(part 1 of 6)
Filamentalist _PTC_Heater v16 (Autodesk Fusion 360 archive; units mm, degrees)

design "Filamentalist _PTC_Heater" references "rocker switch 1", "Anycubic_Photon_Heater_Lid_v2", "heater element", "EL90005--STD--Power Supply 10A 12V (Bicolt Automática 120W)", "Mini Rocker Switch", "Switch,rocker,SPST,black,Iluminated", "1W1209WK", "Rocker Switch - Arcolectric R13 112C AAA"
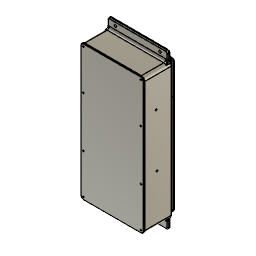
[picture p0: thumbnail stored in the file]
description: STEP AP203
part number: Anycubic Photo Heater Chassis v2
part number: Anycubic Photon Heater Lid
extrude "Extrude1" new body blind -2
extrude "Extrude2" new body blind 2
extrude "Extrude3" add blind 2
fillet "Fillet1" radius 2
extrude "Extrude4" cut blind 70
extrude "Extrude5" cut blind -20
offset_faces "OffsetFaces1" distance -0.5
offset_faces "OffsetFaces2" distance -0.5
offset_faces "OffsetFaces3" distance -0.5
offset_faces "OffsetFaces4" distance -0.5
scale "Scale1" ScaleFactor 0.97
extrude "Extrude6" cut blind -6
mirror "Mirror1"
move "Move1"
extrude "Extrude7" cut blind 100
move "Move2"
combine "Combine1"
extrude "Extrude9" cut distance 20
extrude "Extrude8" cut blind -10
move "Move3"
combine "Combine2"
extrude "Extrude10" new body blind 3
extrude "Extrude11" new body blind 3
extrude "Extrude12" new body blind 3
extrude "Extrude13" new body blind 3
extrude "Extrude14" new body blind 3
extrude "Extrude15" new body blind 3
extrude "Extrude16" new body blind 3
extrude "Extrude17" cut distance -340
move "Move4"
move "Move5"
combine "Combine3"
combine "Combine4"
extrude "Extrude18" cut blind -40
move "Move6"
extrude "Extrude19" add blind 10
extrude "Extrude20" new body blind 3
extrude "Extrude21" new body blind 3
extrude "Extrude22" new body blind 3
extrude "Extrude23" new body blind 3
extrude "Extrude24" new body blind 3
extrude "Extrude25" new body blind 3
component_insert "Component Insert4"
component_insert "Component Insert5"
component_insert "Component Insert6"
component_insert "Component Insert7"
component_insert "Component Insert8"
component_insert "Component Insert9"
remove_instance "RemoveInstance1"
component_insert "Component Insert10"
remove_instance "RemoveInstance2"
remove_instance "RemoveInstance3"
component_insert "Component Insert11"
remove_body "RemoveBody14"
remove_body "RemoveBody15"
remove_body "RemoveBody16"
remove_body "RemoveBody17"
remove_body "RemoveBody18"
remove_body "RemoveBody19"
remove_body "RemoveBody20"
remove_body "RemoveBody21"
remove_body "RemoveBody22"
remove_body "RemoveBody23"
remove_body "RemoveBody24"
remove_body "RemoveBody25"
remove_body "RemoveBody26"
remove_body "RemoveBody27"
remove_body "RemoveBody28"
base_feature "Base Feature1"
remove_instance "RemoveInstance4"
remove_instance "RemoveInstance5"
component_insert "Component Insert13"
position "Position5"
mirror "Mirror1" mirrorStitchTolerance 0.1
sketch "Sketch121" plane through (0, 129.2387, 0) normal (0, -1, 0) x axis (1, 0, 0)
  line L1 (48.1051, -74.1426) -> (50.0646, -75.3199)
  line L2 (57.2625, -58.9021) -> (48.1051, -74.1426)
  line L3 (59.222, -60.0795) -> (57.2625, -58.9021)
  line L4 (110.6429, 25.4992) -> (59.222, -60.0795)
  line L5 (111.3513, 73.7538) -> (111.3513, 28.0538)
  line L6 (-5.4087, 78.7138) -> (106.3913, 78.7138)
  line L7 (-10.3687, 55.8538) -> (-10.3687, 73.7538)
  line L8 (-7.8287, 55.8538) -> (-10.3687, 55.8538)
  line L9 (-7.8287, 22.1988) -> (-7.8287, 55.8538)
  line L10 (-10.3687, 22.1988) -> (-7.8287, 22.1988)
  line L11 (-10.3687, -6.9872) -> (-10.3687, 22.1988)
  line L12 (-4.5267, -6.9872) -> (-10.3687, -6.9872)
  line L13 (-4.5267, -36.7052) -> (-4.5267, -6.9872)
  line L14 (-10.3687, -36.7052) -> (-4.5267, -36.7052)
  line L15 (-10.3687, -64.1372) -> (-10.3687, -36.7052)
  line L16 (-4.5267, -64.1372) -> (-10.3687, -64.1372)
  line L17 (-4.5267, -93.8552) -> (-4.5267, -64.1372)
  line L18 (-10.3687, -93.8552) -> (-4.5267, -93.8552)
  line L19 (-10.3687, -103.2462) -> (-10.3687, -93.8552)
  line L20 (27.4983, -108.2062) -> (-5.4087, -108.2062)
  line L21 (50.0646, -75.3199) -> (31.7499, -105.8008)
  line L22 (71.2365, 31.181) -> (75.4807, 26.9368)
  line L23 (75.4808, 55.779) -> (71.2365, 51.5347)
  line L24 (44.602, 56.4579) -> (40.3585, 60.7014)
  line L25 (40.3585, 22.0143) -> (44.602, 26.2578)
  line L26 (45.2808, 25.579) -> (41.0373, 21.3355)
  line L27 (79.7243, 21.3355) -> (75.4809, 25.579)
  line L28 (69.8785, 31.1814) -> (65.6314, 35.4285)
  line L29 (55.1303, 35.4285) -> (50.8832, 31.1814)
  line L30 (59.7021, 41.3578) -> (55.1317, 45.9282)
  line L31 (55.1317, 36.7875) -> (59.7021, 41.3578)
  line L32 (66.3102, 36.1073) -> (70.5573, 31.8602)
  line L33 (70.5573, 50.8555) -> (66.3102, 46.6084)
  line L34 (61.0596, 41.3578) -> (65.63, 36.7875)
  line L35 (65.63, 45.9282) -> (61.0596, 41.3578)
  line L36 (65.6314, 47.2872) -> (69.8785, 51.5343)
  line L37 (50.8832, 51.5343) -> (55.1303, 47.2872)
  line L38 (60.3808, 42.0366) -> (64.9512, 46.607)
  line L39 (55.8105, 46.607) -> (60.3808, 42.0366)
  line L40 (41.0373, 61.3802) -> (45.2808, 57.1367)
  line L41 (75.4809, 57.1367) -> (79.7244, 61.3802)
  line L42 (70.5577, 52.2135) -> (74.802, 56.4578)
  line L43 (45.9597, 56.4578) -> (50.204, 52.2135)
  line L44 (60.3808, 40.6791) -> (55.8105, 36.1087)
  line L45 (64.9512, 36.1087) -> (60.3808, 40.6791)
  line L46 (45.281, 26.9368) -> (49.5252, 31.181)
  line L47 (49.5252, 51.5347) -> (45.2809, 55.779)
  line L48 (74.8019, 26.258) -> (70.5577, 30.5022)
  line L49 (50.204, 30.5022) -> (45.9598, 26.258)
  line L50 (50.2044, 31.8602) -> (54.4515, 36.1073)
  line L51 (54.4515, 46.6084) -> (50.2044, 50.8555)
  line L52 (76.1597, 26.2578) -> (80.4031, 22.0143)
  line L53 (80.4032, 60.7014) -> (76.1597, 56.4579)
  line L54 (133.3621, 41.3578) -> (104.5086, 41.3578)
  line L55 (133.3621, -4.4508) -> (133.3621, 41.3578)
  line L56 (104.5086, -4.4508) -> (133.3621, -4.4508)
  line L57 (104.5086, 41.3578) -> (104.5086, -4.4508)
  line L58 (150.5116, 41.3578) -> (104.5086, 41.3578)
  line L59 (150.5116, -14.1468) -> (150.5116, 41.3578)
  line L60 (104.5086, -14.1468) -> (150.5116, -14.1468)
  line L61 (104.5086, 41.3578) -> (104.5086, -14.1468)
  line L62 (100.5085, 41.3578) -> (104.5086, 41.3578)
  line L63 (100.5085, -14.1468) -> (100.5085, 41.3578)
  line L64 (104.5086, -14.1468) -> (100.5085, -14.1468)
  line L65 (104.5086, 41.3578) -> (104.5086, -14.1468)
  line L66 (50, -104.5945) -> (19.4151, -104.5945)
  line L67 (50, -130) -> (50, -104.5945)
  line L68 (19.4151, -130) -> (50, -130)
  line L69 (19.4151, -104.5945) -> (19.4151, -130)
  line L70 (31.7499, -99.5133) -> (100.5085, 13.6055)
  line L71 (27.4983, -108.2062) -> (31.7499, -99.5133)
  line L72 (50, -130) -> (117.9168, -14.1468)
  line L73 (236.4848, -122.3783) -> (150.5116, 16.8124)
  line L74 (221.251, -97.7148) -> (236.4848, -122.3783)
  line L75 (233.1462, -102.3471) -> (221.251, -97.7148)
  line L76 (237.9019, -110.0465) -> (233.1462, -102.3471)
  line L77 (237.9019, -132.6507) -> (237.9019, -110.0465)
  line L78 (185, -125) -> (237.9019, -132.6507)
  line L79 (138.8972, -14.1468) -> (185, -125)
  line L80 (25.5423, -99.5133) -> (32.8922, -97.1777)
  line L81 (19.4151, -104.5945) -> (25.5423, -99.5133)
  line L82 (34.9411, -96.5266) -> (32.3455, -97.3514)
  arc A1 centre (106.3913, 28.0538) radius 4.96 clockwise from (111.3513, 28.0538) to (110.6429, 25.4992)
  arc A2 centre (106.3913, 73.7538) radius 4.96 clockwise from (106.3913, 78.7138) to (111.3513, 73.7538)
  arc A3 centre (-5.4087, 73.7538) radius 4.96 clockwise from (-10.3687, 73.7538) to (-5.4087, 78.7138)
  arc A4 centre (-5.4087, -103.2462) radius 4.96 clockwise from (-5.4087, -108.2062) to (-10.3687, -103.2462)
  arc A5 centre (27.4983, -103.2462) radius 4.96 clockwise from (31.7499, -105.8008) to (27.4983, -108.2062)
  arc A6 centre (60.3808, 41.3579) radius 20.88 clockwise from (75.4808, 55.779) to (75.4807, 26.9368)
  arc A7 centre (60.3809, 41.3578) radius 14.88 clockwise from (71.2365, 51.5347) to (71.2365, 31.181)
  arc A8 centre (60.3808, 41.3579) radius 27.84 clockwise from (40.3585, 22.0143) to (40.3585, 60.7014)
  arc A9 centre (60.3809, 41.3578) radius 21.84 clockwise from (44.602, 26.2578) to (44.602, 56.4579)
  arc A10 centre (60.3808, 41.3579) radius 27.84 clockwise from (79.7243, 21.3355) to (41.0373, 21.3355)
  arc A11 centre (60.3809, 41.3578) radius 21.84 clockwise from (75.4809, 25.579) to (45.2808, 25.579)
  circle C1 centre (85.3808, 16.3578) radius 2.2
  arc A12 centre (60.3808, 41.3579) radius 7.92 clockwise from (65.6314, 35.4285) to (55.1303, 35.4285)
  arc A13 centre (60.3809, 41.3579) radius 13.92 clockwise from (69.8785, 31.1814) to (50.8832, 31.1814)
  arc A14 centre (60.3808, 41.3578) radius 6.96 clockwise from (55.1317, 36.7875) to (55.1317, 45.9282)
  arc A15 centre (60.3809, 41.3579) radius 13.92 clockwise from (70.5573, 50.8555) to (70.5573, 31.8602)
  arc A16 centre (60.3808, 41.3579) radius 7.92 clockwise from (66.3102, 46.6084) to (66.3102, 36.1073)
  arc A17 centre (60.3808, 41.3578) radius 6.96 clockwise from (65.63, 45.9282) to (65.63, 36.7875)
  arc A18 centre (60.3809, 41.3579) radius 13.92 clockwise from (50.8832, 51.5343) to (69.8785, 51.5343)
  arc A19 centre (60.3808, 41.3579) radius 7.92 clockwise from (55.1303, 47.2872) to (65.6314, 47.2872)
  arc A20 centre (60.3808, 41.3578) radius 6.96 clockwise from (55.8105, 46.607) to (64.9512, 46.607)
  arc A21 centre (60.3809, 41.3578) radius 21.84 clockwise from (45.2808, 57.1367) to (75.4809, 57.1367)
  arc A22 centre (60.3808, 41.3579) radius 27.84 clockwise from (41.0373, 61.3802) to (79.7244, 61.3802)
  arc A23 centre (60.3808, 41.3579) radius 20.88 clockwise from (45.9597, 56.4578) to (74.802, 56.4578)
  arc A24 centre (60.3809, 41.3578) radius 14.88 clockwise from (50.204, 52.2135) to (70.5577, 52.2135)
  arc A25 centre (60.3808, 41.3578) radius 6.96 clockwise from (64.9512, 36.1087) to (55.8105, 36.1087)
  circle C2 centre (85.3808, 66.3578) radius 2.2
  circle C3 centre (35.3808, 66.3578) radius 2.2
  circle C4 centre (35.3808, 16.3578) radius 2.2
  arc A26 centre (60.3809, 41.3578) radius 14.88 clockwise from (49.5252, 31.181) to (49.5252, 51.5347)
  arc A27 centre (60.3808, 41.3579) radius 20.88 clockwise from (45.281, 26.9368) to (45.2809, 55.779)
  arc A28 centre (60.3809, 41.3578) radius 14.88 clockwise from (70.5577, 30.5022) to (50.204, 30.5022)
  arc A29 centre (60.3808, 41.3579) radius 20.88 clockwise from (74.8019, 26.258) to (45.9598, 26.258)
  arc A30 centre (60.3808, 41.3579) radius 7.92 clockwise from (54.4515, 36.1073) to (54.4515, 46.6084)
  arc A31 centre (60.3809, 41.3579) radius 13.92 clockwise from (50.2044, 31.8602) to (50.2044, 50.8555)
  arc A32 centre (60.3808, 41.3579) radius 27.84 clockwise from (80.4032, 60.7014) to (80.4031, 22.0143)
  arc A33 centre (60.3809, 41.3578) radius 21.84 clockwise from (76.1597, 56.4579) to (76.1597, 26.2578)
  circle C5 centre (26.6464, -73.9162) radius 3.175
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  point P181 (100.5085, 13.6055)
  point P30 (27.4983, -108.2062)
  point P183 (27.4983, -108.2062)
  point P184 (117.9168, -14.1468)
  point P185 (150.5116, 16.8124)
  point P187 (221.251, -97.7148)
  point P192 (138.8972, -14.1468)
  point P195 (32.3455, -97.3514)
  horizontal L54
  vertical L55
  horizontal L56
  vertical L57
  horizontal L58
  vertical L59
  horizontal L60
  vertical L61
  horizontal L62
  vertical L63
  horizontal L64
  vertical L65
  horizontal L66
  vertical L67
  horizontal L68
  vertical L69
  midpoint L63 P181
  coincident P30 P183
  coincident L60 P184
  coincident L59 P185
  coincident L73 P187
  parallel L73 L76
  vertical L77
  coincident L60 P192
  coincident L80 P195
  parallel L80 L82
extrude "Extrude1" cut sketch "Sketch121" profile of L1 L2 L3 L4 A1 L5 L20 A5 L21 L54 L55 L56 L57 L58 L59 L60 L61 L62 L63 L64 L65 L66 L67 L68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 distance 120
remove_body "RemoveBody1"
remove_body "RemoveBody2"
sketch "Sketch122" plane through (0, 129.2387, 0) normal (0, -1, 0) x axis (1, 0, 0)
  line L1 (150.5116, 41.3578) -> (141.4313, 41.3578)
  line L2 (150.5116, 16.8124) -> (150.5116, 41.3578)
  line L3 (215.4468, -88.3178) -> (150.5116, 16.8124)
  line L4 (221.251, -97.7148) -> (216.1448, -89.4478)
  line L5 (233.1462, -102.3471) -> (221.251, -97.7148)
  line L6 (236.7652, -108.2062) -> (233.1462, -102.3471)
  line L7 (258.1913, -108.2062) -> (236.7652, -108.2062)
  line L8 (263.1513, -93.8552) -> (263.1513, -103.2462)
  line L9 (257.3093, -93.8552) -> (263.1513, -93.8552)
  line L10 (257.3093, -64.1372) -> (257.3093, -93.8552)
  line L11 (263.1513, -64.1372) -> (257.3093, -64.1372)
  line L12 (263.1513, -36.7052) -> (263.1513, -64.1372)
  line L13 (257.3093, -36.7052) -> (263.1513, -36.7052)
  line L14 (257.3093, -6.9872) -> (257.3093, -36.7052)
  line L15 (263.1513, -6.9872) -> (257.3093, -6.9872)
  line L16 (263.1513, 22.1988) -> (263.1513, -6.9872)
  line L17 (260.6113, 22.1988) -> (263.1513, 22.1988)
  line L18 (260.6113, 55.8538) -> (260.6113, 22.1988)
  line L19 (263.1513, 55.8538) -> (260.6113, 55.8538)
  line L20 (263.1513, 73.7538) -> (263.1513, 55.8538)
  line L21 (146.3913, 78.7138) -> (258.1913, 78.7138)
  line L22 (141.4313, 41.3578) -> (141.4313, 73.7538)
  line L23 (176.6229, 56.4579) -> (172.3795, 60.7014)
  line L24 (172.3795, 22.0143) -> (176.6229, 26.2578)
  line L25 (202.5782, 50.8555) -> (198.3312, 46.6084)
  line L26 (198.3312, 36.1073) -> (202.5782, 31.8602)
  line L27 (206.8229, 26.258) -> (202.5786, 30.5022)
  line L28 (182.2249, 30.5022) -> (177.9807, 26.258)
  line L29 (207.5017, 55.779) -> (203.2574, 51.5347)
  line L30 (203.2574, 31.181) -> (207.5017, 26.9368)
  line L31 (192.4018, 40.6791) -> (187.8314, 36.1087)
  line L32 (196.9721, 36.1087) -> (192.4018, 40.6791)
  line L33 (202.5786, 52.2135) -> (206.8229, 56.4578)
  line L34 (177.9807, 56.4578) -> (182.2249, 52.2135)
  line L35 (173.0583, 61.3802) -> (177.3017, 57.1367)
  line L36 (207.5018, 57.1367) -> (211.7453, 61.3802)
  line L37 (192.4018, 42.0366) -> (196.9721, 46.607)
  line L38 (187.8314, 46.607) -> (192.4018, 42.0366)
  line L39 (197.6524, 47.2872) -> (201.8994, 51.5343)
  line L40 (182.9041, 51.5343) -> (187.1512, 47.2872)
  line L41 (191.723, 41.3578) -> (187.1526, 45.9282)
  line L42 (187.1526, 36.7875) -> (191.723, 41.3578)
  line L43 (186.4724, 46.6084) -> (182.2253, 50.8555)
  line L44 (182.2253, 31.8602) -> (186.4724, 36.1073)
  line L45 (193.0806, 41.3578) -> (197.6509, 36.7875)
  line L46 (197.6509, 45.9282) -> (193.0806, 41.3578)
  line L47 (201.8994, 31.1814) -> (197.6524, 35.4285)
  line L48 (187.1512, 35.4285) -> (182.9041, 31.1814)
  line L49 (177.3017, 25.579) -> (173.0583, 21.3355)
  line L50 (211.7453, 21.3355) -> (207.5018, 25.579)
  line L51 (208.1806, 26.2578) -> (212.4241, 22.0143)
  line L52 (212.4241, 60.7014) -> (208.1806, 56.4579)
  line L53 (181.5461, 51.5347) -> (177.3019, 55.779)
  line L54 (177.3019, 26.9368) -> (181.5461, 31.181)
  line L55 (110, 110) -> (240, 110)
  line L56 (110, 0) -> (110, 110)
  line L57 (240, 0) -> (110, 0)
  line L58 (240, 110) -> (240, 0)
  circle C1 centre (241.5342, -100.5862) radius 3.175
  circle C2 centre (233.8352, -51.6912) radius 3.175
  circle C3 centre (226.1363, -47.2462) radius 3.175
  circle C4 centre (226.1363, -38.3562) radius 3.175
  circle C5 centre (218.4373, -33.9112) radius 3.175
  circle C6 centre (218.4373, -25.0212) radius 3.175
  circle C7 centre (210.7383, -20.5762) radius 3.175
  circle C8 centre (249.2332, -69.4712) radius 3.175
  circle C9 centre (249.2332, -60.5812) radius 3.175
  circle C10 centre (233.8352, -60.5812) radius 3.175
  circle C11 centre (241.5342, -65.0262) radius 3.175
  circle C12 centre (241.5342, -73.9162) radius 3.175
  circle C13 centre (249.2332, -78.3612) radius 3.175
  circle C14 centre (203.0394, -25.0212) radius 3.175
  circle C15 centre (210.7383, -29.4662) radius 3.175
  circle C16 centre (210.7383, -38.3562) radius 3.175
  circle C17 centre (218.4373, -42.8012) radius 3.175
  circle C18 centre (249.2332, -33.9112) radius 3.175
  circle C19 centre (233.8352, -25.0212) radius 3.175
  circle C20 centre (241.5342, -29.4662) radius 3.175
  circle C21 centre (241.5342, -38.3562) radius 3.175
  circle C22 centre (249.2332, -25.0212) radius 3.175
  circle C23 centre (241.5342, -20.5762) radius 3.175
  circle C24 centre (241.5342, -56.1362) radius 3.175
  circle C25 centre (241.5342, -47.2462) radius 3.175
  circle C26 centre (233.8352, -42.8012) radius 3.175
  circle C27 centre (233.8352, -33.9112) radius 3.175
  circle C28 centre (226.1363, -29.4662) radius 3.175
  circle C29 centre (226.1363, -20.5762) radius 3.175
  circle C30 centre (249.2332, -51.6912) radius 3.175
  circle C31 centre (249.2332, -42.8012) radius 3.175
  circle C32 centre (226.1363, -82.8062) radius 3.175
  circle C33 centre (233.8352, -87.2512) radius 3.175
  circle C34 centre (241.5342, -91.6962) radius 3.175
  circle C35 centre (249.2332, -96.1412) radius 3.175
  circle C36 centre (187.6414, -25.0212) radius 3.175
  circle C37 centre (187.6414, -33.9112) radius 3.175
  circle C38 centre (195.3404, -38.3562) radius 3.175
  circle C39 centre (195.3404, -47.2462) radius 3.175
  circle C40 centre (203.0394, -51.6912) radius 3.175
  circle C41 centre (203.0394, -60.5812) radius 3.175
  circle C42 centre (210.7383, -65.0262) radius 3.175
  circle C43 centre (210.7383, -73.9162) radius 3.175
  circle C44 centre (218.4373, -78.3612) radius 3.175
  arc A1 centre (218.4373, -87.2512) radius 3.175 clockwise from (215.4468, -88.3178) to (216.1448, -89.4478)
  arc A2 centre (258.1913, -103.2462) radius 4.96 clockwise from (263.1513, -103.2462) to (258.1913, -108.2062)
  arc A3 centre (258.1913, 73.7538) radius 4.96 clockwise from (258.1913, 78.7138) to (263.1513, 73.7538)
  arc A4 centre (146.3913, 73.7538) radius 4.96 clockwise from (141.4313, 73.7538) to (146.3913, 78.7138)
  circle C45 centre (226.1363, -91.6962) radius 3.175
  circle C46 centre (233.8352, -96.1412) radius 3.175
  circle C47 centre (233.8352, -78.3612) radius 3.175
  circle C48 centre (241.5342, -82.8062) radius 3.175
  circle C49 centre (249.2332, -87.2512) radius 3.175
  circle C50 centre (195.3404, -20.5762) radius 3.175
  circle C51 centre (233.8352, -69.4712) radius 3.175
  circle C52 centre (226.1363, -65.0262) radius 3.175
  circle C53 centre (226.1363, -56.1362) radius 3.175
  circle C54 centre (218.4373, -51.6912) radius 3.175
  circle C55 centre (195.3404, -29.4662) radius 3.175
  circle C56 centre (203.0394, -33.9112) radius 3.175
  circle C57 centre (203.0394, -42.8012) radius 3.175
  circle C58 centre (210.7383, -47.2462) radius 3.175
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  horizontal L55
  vertical L56
  horizontal L57
  vertical L58
extrude "Extrude2" cut sketch "Sketch122" distance 60
delete_face "DeleteFace1"
delete_face "DeleteFace2"
delete_face "DeleteFace3"
delete_face "DeleteFace4"
delete_face "DeleteFace5"
delete_face "DeleteFace6"
delete_face "DeleteFace7"
sketch "Sketch123" plane through (263.1513, 0, 0) normal (-1, 0, 0) x axis (0, -1, 0)
  line L1 (-85.2967, 73.7538) -> (-85.2967, 52.2724)
  line L2 (-129.2387, 73.7538) -> (-85.2967, 73.7538)
  line L3 (-129.2387, -103.2462) -> (-129.2387, 73.7538)
  line L4 (-85.2967, -103.2462) -> (-129.2387, -103.2462)
  line L5 (-85.2967, 25.7802) -> (-85.2967, -103.2462)
  line L6 (-77.2576, 25.7802) -> (-85.2967, 25.7802)
  line L7 (-77.2576, 52.2724) -> (-77.2576, 25.7802)
  line L8 (-85.2967, 52.2724) -> (-77.2576, 52.2724)
  line L9 (-85.2967, 65.0066) -> (-122.5621, 65.0066)
  line L10 (-85.2967, -94.8647) -> (-85.2967, 65.0066)
  line L11 (-122.5621, -94.8647) -> (-85.2967, -94.8647)
  line L12 (-122.5621, 65.0066) -> (-122.5621, -94.8647)
  point P12 (-85.2967, -94.8647)
  horizontal L9
  vertical L10
  horizontal L11
  vertical L12
  coincident L5 P12
extrude "Extrude3" cut sketch "Sketch123" profile of L1 L5 L9 L10 L11 L12 against normal blind 20
sketch "Sketch124" plane through (265.6913, 0, 0) normal (1, 0, 0) x axis (0, 1, 0)
  line L1 (85.2967, -61.2162) -> (85.2967, -71.7583)
  line L2 (85.072, -61.2162) -> (85.2967, -61.2162)
  line L3 (85.072, -59.5646) -> (85.072, -61.2162)
  curve K1 (85.072, -59.5646) -> (84.1256, -57.0155)
  curve K2 (84.1256, -57.0155) -> (83.4601, -57.2521)
  line L4 (83.1182, -55.8584) -> (83.4601, -57.2521)
  curve K3 (83.1182, -55.8584) -> (83.9654, -55.5501)
  curve K4 (83.9654, -55.5501) -> (85.072, -56.4247)
  line L5 (85.072, -55.6478) -> (85.072, -56.4247)
  line L6 (85.2967, -55.6478) -> (85.072, -55.6478)
  line L7 (85.2967, -29.0841) -> (85.2967, -55.6478)
  line L8 (85.2967, -4.0662) -> (85.2967, -14.6083)
  line L9 (84.5836, -4.0662) -> (85.2967, -4.0662)
  line L10 (84.5836, -2.4146) -> (84.5836, -4.0662)
  curve K5 (84.5836, -2.4146) -> (83.6372, 0.1345)
  curve K6 (83.6372, 0.1345) -> (82.9717, -0.1021)
  line L11 (82.6297, 1.2916) -> (82.9717, -0.1021)
  curve K7 (82.6297, 1.2916) -> (83.4769, 1.5999)
  curve K8 (83.4769, 1.5999) -> (84.5836, 0.7253)
  line L12 (84.5836, 1.5022) -> (84.5836, 0.7253)
  line L13 (85.2967, 1.5022) -> (84.5836, 1.5022)
  line L14 (85.2967, 65.0066) -> (85.2967, 1.5022)
  line L15 (122.5621, 65.0066) -> (85.2967, 65.0066)
  line L16 (122.5621, -94.8647) -> (122.5621, 65.0066)
  line L17 (85.2967, -94.8647) -> (122.5621, -94.8647)
  line L18 (85.2967, -86.2341) -> (85.2967, -94.8647)
  line L19 (127.2387, 73.7538) -> (127.2387, -103.2462)
  line L20 (72.0887, 73.7538) -> (127.2387, 73.7538)
  line L21 (72.0887, -103.2462) -> (72.0887, 73.7538)
  line L22 (127.2387, -103.2462) -> (72.0887, -103.2462)
  line L23 (80, 11.4296) -> (85.2967, 11.4296)
  line L24 (80, -90) -> (80, 11.4296)
  line L25 (85.2967, -90) -> (80, -90)
  line L26 (85.2967, 11.4296) -> (85.2967, -90)
  arc A1 centre (99.1397, -21.8462) radius 15.621 clockwise from (85.2967, -29.0841) to (85.2967, -14.6083)
  arc A2 centre (99.1397, -78.9962) radius 15.621 clockwise from (85.2967, -86.2341) to (85.2967, -71.7583)
  point P36 (85.2967, 11.4296)
  horizontal L23
  vertical L24
  horizontal L25
  vertical L26
  coincident L14 P36
extrude "Extrude4" cut sketch "Sketch124" profile of L1 L2 L3 K1 K2 L4 K3 K4 L5 L6 L7 A1 L8 L9 L10 K5 K6 L11 K7 K8 L12 L13 L14 L18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 against normal blind 1
delete_face "DeleteFace8"
delete_face "DeleteFace9"
delete_face "DeleteFace10"
delete_face "DeleteFace11"
sketch "Sketch125" plane through (0, 0, 52.2724) normal (0, 0, -1) x axis (1, 0, 0)
  line L1 (262.2877, -84.4331) -> (262.2877, -77.2576)
  line L2 (263.1513, -85.2967) -> (262.2877, -84.4331)
  line L3 (263.1513, -77.2576) -> (263.1513, -85.2967)
  line L4 (262.2877, -77.2576) -> (263.1513, -77.2576)
extrude "Extrude5" add sketch "Sketch125" along normal blind 28
move "Move1"
sketch "Sketch126" plane through (0, 129.2387, 0) normal (0, -1, 0) x axis (1, 0, 0)
  line L1 (111.1513, 73.7538) -> (111.1513, -103.2462)
  line L2 (88, 78.7138) -> (106.1913, 78.7138)
  line L3 (88, 0) -> (88, 78.7138)
  line L4 (8.896, 0) -> (88, 0)
  line L5 (63.4468, -88.3178) -> (8.896, 0)
  line L6 (69.251, -97.7148) -> (64.1448, -89.4478)
  line L7 (81.1462, -102.3471) -> (69.251, -97.7148)
  line L8 (84.7652, -108.2062) -> (81.1462, -102.3471)
  line L9 (106.1913, -108.2062) -> (84.7652, -108.2062)
  arc A1 centre (106.1913, 73.7538) radius 4.96 clockwise from (106.1913, 78.7138) to (111.1513, 73.7538)
  arc A2 centre (66.4373, -87.2512) radius 3.175 clockwise from (63.4468, -88.3178) to (64.1448, -89.4478)
  arc A3 centre (106.1913, -103.2462) radius 4.96 clockwise from (111.1513, -103.2462) to (106.1913, -108.2062)
  circle C1 centre (89.5342, -91.6962) radius 3.175
  circle C2 centre (74.1363, -73.9162) radius 3.175
  circle C3 centre (66.4373, -69.4712) radius 3.175
  circle C4 centre (66.4373, -60.5812) radius 3.175
  circle C5 centre (58.7383, -56.1362) radius 3.175
  circle C6 centre (58.7383, -47.2462) radius 3.175
  circle C7 centre (51.0394, -42.8012) radius 3.175
  circle C8 centre (51.0394, -33.9112) radius 3.175
  circle C9 centre (43.3404, -29.4662) radius 3.175
  circle C10 centre (66.4373, -51.6912) radius 3.175
  circle C11 centre (74.1363, -56.1362) radius 3.175
  circle C12 centre (74.1363, -65.0262) radius 3.175
  circle C13 centre (81.8352, -69.4712) radius 3.175
  circle C14 centre (43.3404, -20.5762) radius 3.175
  circle C15 centre (97.2332, -87.2512) radius 3.175
  circle C16 centre (89.5342, -82.8062) radius 3.175
  circle C17 centre (81.8352, -78.3612) radius 3.175
  circle C18 centre (81.8352, -96.1412) radius 3.175
  circle C19 centre (74.1363, -91.6962) radius 3.175
  circle C20 centre (66.4373, -78.3612) radius 3.175
  circle C21 centre (58.7383, -73.9162) radius 3.175
  circle C22 centre (58.7383, -65.0262) radius 3.175
  circle C23 centre (51.0394, -60.5812) radius 3.175
  circle C24 centre (51.0394, -51.6912) radius 3.175
  circle C25 centre (43.3404, -47.2462) radius 3.175
  circle C26 centre (43.3404, -38.3562) radius 3.175
  circle C27 centre (35.6414, -33.9112) radius 3.175
  circle C28 centre (35.6414, -25.0212) radius 3.175
  circle C29 centre (97.2332, -96.1412) radius 3.175
  circle C30 centre (81.8352, -87.2512) radius 3.175
  circle C31 centre (74.1363, -82.8062) radius 3.175
  circle C32 centre (97.2332, -42.8012) radius 3.175
  circle C33 centre (97.2332, -51.6912) radius 3.175
  circle C34 centre (74.1363, -20.5762) radius 3.175
  circle C35 centre (74.1363, -29.4662) radius 3.175
  circle C36 centre (81.8352, -33.9112) radius 3.175
  circle C37 centre (81.8352, -42.8012) radius 3.175
  circle C38 centre (89.5342, -47.2462) radius 3.175
  circle C39 centre (89.5342, -56.1362) radius 3.175
  circle C40 centre (89.5342, -20.5762) radius 3.175
  circle C41 centre (97.2332, -25.0212) radius 3.175
  circle C42 centre (89.5342, -29.4662) radius 3.175
  circle C43 centre (81.8352, -25.0212) radius 3.175
  circle C44 centre (66.4373, -42.8012) radius 3.175
  circle C45 centre (58.7383, -38.3562) radius 3.175
  circle C46 centre (58.7383, -29.4662) radius 3.175
  circle C47 centre (51.0394, -25.0212) radius 3.175
  circle C48 centre (97.2332, -78.3612) radius 3.175
  circle C49 centre (89.5342, -73.9162) radius 3.175
  circle C50 centre (89.5342, -65.0262) radius 3.175
  circle C51 centre (81.8352, -60.5812) radius 3.175
  circle C52 centre (97.2332, -60.5812) radius 3.175
  circle C53 centre (97.2332, -69.4712) radius 3.175
  circle C54 centre (58.7383, -20.5762) radius 3.175
  circle C55 centre (66.4373, -25.0212) radius 3.175
  circle C56 centre (66.4373, -33.9112) radius 3.175
  circle C57 centre (74.1363, -38.3562) radius 3.175
  circle C58 centre (74.1363, -47.2462) radius 3.175
  circle C59 centre (81.8352, -51.6912) radius 3.175
  circle C60 centre (89.5342, -100.5862) radius 3.175
  circle C61 centre (97.2332, -33.9112) radius 3.175
  circle C62 centre (89.5342, -38.3562) radius 3.175
  circle C63 centre (66.4373, -87.2512) radius 3.175
  concentric A2 C63
extrude "Extrude26" new body sketch "Sketch126" profile of A2 C1 C2 C3 C4 C5 C6 C7 C8 C9 C10 C11 C12 C13 C14 C15 C16 C17 C18 C19 C20 C21 C22 C23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 along normal blind 5
sketch "Sketch127" plane through (0, 129.2387, 0) normal (0, -1, 0) x axis (1, 0, 0)
  line L1 (111.1513, 73.7538) -> (111.1513, -103.2462)
  line L2 (88, 78.7138) -> (106.1913, 78.7138)
  line L3 (88, 0) -> (88, 78.7138)
  line L4 (8.896, 0) -> (88, 0)
  line L5 (63.4468, -88.3178) -> (8.896, 0)
  line L6 (69.251, -97.7148) -> (64.1448, -89.4478)
  line L7 (81.1462, -102.3471) -> (69.251, -97.7148)
  line L8 (84.7652, -108.2062) -> (81.1462, -102.3471)
  line L9 (106.1913, -108.2062) -> (84.7652, -108.2062)
  arc A1 centre (106.1913, 73.7538) radius 4.96 clockwise from (106.1913, 78.7138) to (111.1513, 73.7538)
  arc A2 centre (66.4373, -87.2512) radius 3.175 clockwise from (63.4468, -88.3178) to (64.1448, -89.4478)
  arc A3 centre (106.1913, -103.2462) radius 4.96 clockwise from (111.1513, -103.2462) to (106.1913, -108.2062)
  circle C1 centre (89.5342, -91.6962) radius 3.175
  circle C2 centre (74.1363, -73.9162) radius 3.175
  circle C3 centre (66.4373, -69.4712) radius 3.175
  circle C4 centre (66.4373, -60.5812) radius 3.175
  circle C5 centre (58.7383, -56.1362) radius 3.175
  circle C6 centre (58.7383, -47.2462) radius 3.175
  circle C7 centre (51.0394, -42.8012) radius 3.175
  circle C8 centre (51.0394, -33.9112) radius 3.175
  circle C9 centre (43.3404, -29.4662) radius 3.175
  circle C10 centre (66.4373, -51.6912) radius 3.175
  circle C11 centre (74.1363, -56.1362) radius 3.175
  circle C12 centre (74.1363, -65.0262) radius 3.175
  circle C13 centre (81.8352, -69.4712) radius 3.175
  circle C14 centre (43.3404, -20.5762) radius 3.175
  circle C15 centre (97.2332, -87.2512) radius 3.175
  circle C16 centre (89.5342, -82.8062) radius 3.175
  circle C17 centre (81.8352, -78.3612) radius 3.175
  circle C18 centre (81.8352, -96.1412) radius 3.175
  circle C19 centre (74.1363, -91.6962) radius 3.175
  circle C20 centre (66.4373, -78.3612) radius 3.175
  circle C21 centre (58.7383, -73.9162) radius 3.175
  circle C22 centre (58.7383, -65.0262) radius 3.175
  circle C23 centre (51.0394, -60.5812) radius 3.175
  circle C24 centre (51.0394, -51.6912) radius 3.175
  circle C25 centre (43.3404, -47.2462) radius 3.175
  circle C26 centre (43.3404, -38.3562) radius 3.175
  circle C27 centre (35.6414, -33.9112) radius 3.175
  circle C28 centre (35.6414, -25.0212) radius 3.175
  circle C29 centre (97.2332, -96.1412) radius 3.175
  circle C30 centre (81.8352, -87.2512) radius 3.175
  circle C31 centre (74.1363, -82.8062) radius 3.175
  circle C32 centre (97.2332, -42.8012) radius 3.175
  circle C33 centre (97.2332, -51.6912) radius 3.175
  circle C34 centre (74.1363, -20.5762) radius 3.175
  circle C35 centre (74.1363, -29.4662) radius 3.175
  circle C36 centre (81.8352, -33.9112) radius 3.175
  circle C37 centre (81.8352, -42.8012) radius 3.175
  circle C38 centre (89.5342, -47.2462) radius 3.175
  circle C39 centre (89.5342, -56.1362) radius 3.175
  circle C40 centre (89.5342, -20.5762) radius 3.175
  circle C41 centre (97.2332, -25.0212) radius 3.175
  circle C42 centre (89.5342, -29.4662) radius 3.175
  circle C43 centre (81.8352, -25.0212) radius 3.175
  circle C44 centre (66.4373, -42.8012) radius 3.175
  circle C45 centre (58.7383, -38.3562) radius 3.175
  circle C46 centre (58.7383, -29.4662) radius 3.175
  circle C47 centre (51.0394, -25.0212) radius 3.175
  circle C48 centre (97.2332, -78.3612) radius 3.175
  circle C49 centre (89.5342, -73.9162) radius 3.175
  circle C50 centre (89.5342, -65.0262) radius 3.175
  circle C51 centre (81.8352, -60.5812) radius 3.175
  circle C52 centre (97.2332, -60.5812) radius 3.175
  circle C53 centre (97.2332, -69.4712) radius 3.175
  circle C54 centre (58.7383, -20.5762) radius 3.175
  circle C55 centre (66.4373, -25.0212) radius 3.175
  circle C56 centre (66.4373, -33.9112) radius 3.175
  circle C57 centre (74.1363, -38.3562) radius 3.175
  circle C58 centre (74.1363, -47.2462) radius 3.175
  circle C59 centre (81.8352, -51.6912) radius 3.175
  circle C60 centre (89.5342, -100.5862) radius 3.175
  circle C61 centre (97.2332, -33.9112) radius 3.175
  circle C62 centre (89.5342, -38.3562) radius 3.175
delete_face "DeleteFace12"
delete_face "DeleteFace13"
delete_face "DeleteFace14"
delete_face "DeleteFace15"
offset_faces "OffsetFaces1" distance 68
sketch "Sketch128" plane through (0, 129.2387, 0) normal (0, -1, 0) x axis (1, 0, 0)
  line L1 (76.1597, 26.2578) -> (80.4031, 22.0143)
  line L2 (80.4032, 60.7014) -> (76.1597, 56.4579)
  line L3 (50.2044, 31.8602) -> (54.4515, 36.1073)
  line L4 (54.4515, 46.6084) -> (50.2044, 50.8555)
  line L5 (74.8019, 26.258) -> (70.5577, 30.5022)
  line L6 (50.204, 30.5022) -> (45.9598, 26.258)
  line L7 (45.281, 26.9368) -> (49.5252, 31.181)
  line L8 (49.5252, 51.5347) -> (45.2809, 55.779)
  line L9 (60.3808, 40.6791) -> (55.8105, 36.1087)
  line L10 (64.9512, 36.1087) -> (60.3808, 40.6791)
  line L11 (70.5577, 52.2135) -> (74.802, 56.4578)
  line L12 (45.9597, 56.4578) -> (50.204, 52.2135)
  line L13 (41.0373, 61.3802) -> (45.2808, 57.1367)
  line L14 (75.4809, 57.1367) -> (79.7244, 61.3802)
  line L15 (60.3808, 42.0366) -> (64.9512, 46.607)
  line L16 (55.8105, 46.607) -> (60.3808, 42.0366)
  line L17 (65.6314, 47.2872) -> (69.8785, 51.5343)
  line L18 (50.8832, 51.5343) -> (55.1303, 47.2872)
  line L19 (61.0596, 41.3578) -> (65.63, 36.7875)
  line L20 (65.63, 45.9282) -> (61.0596, 41.3578)
  line L21 (66.3102, 36.1073) -> (70.5573, 31.8602)
  line L22 (70.5573, 50.8555) -> (66.3102, 46.6084)
  line L23 (59.7021, 41.3578) -> (55.1317, 45.9282)
  line L24 (55.1317, 36.7875) -> (59.7021, 41.3578)
  line L25 (69.8785, 31.1814) -> (65.6314, 35.4285)
  line L26 (55.1303, 35.4285) -> (50.8832, 31.1814)
  line L27 (45.2808, 25.579) -> (41.0373, 21.3355)
  line L28 (79.7243, 21.3355) -> (75.4809, 25.579)
  line L29 (44.602, 56.4579) -> (40.3585, 60.7014)
  line L30 (40.3585, 22.0143) -> (44.602, 26.2578)
  line L31 (71.2365, 31.181) -> (75.4807, 26.9368)
  line L32 (75.4808, 55.779) -> (71.2365, 51.5347)
  line L33 (87.4151, -7.9352) -> (87.4151, -108.2062)
  line L34 (100.5085, 13.6055) -> (87.4151, -7.9352)
  line L35 (100.5085, 41.3578) -> (100.5085, 13.6055)
  line L36 (111.3513, 41.3578) -> (100.5085, 41.3578)
  line L37 (111.3513, 73.7538) -> (111.3513, 41.3578)
  line L38 (-5.4087, 78.7138) -> (106.3913, 78.7138)
  line L39 (-10.3687, 55.8538) -> (-10.3687, 73.7538)
  line L40 (-7.8287, 55.8538) -> (-10.3687, 55.8538)
  line L41 (-7.8287, 22.1988) -> (-7.8287, 55.8538)
  line L42 (-10.3687, 22.1988) -> (-7.8287, 22.1988)
  line L43 (-10.3687, -6.9872) -> (-10.3687, 22.1988)
  line L44 (-4.5267, -6.9872) -> (-10.3687, -6.9872)
  line L45 (-4.5267, -36.7052) -> (-4.5267, -6.9872)
  line L46 (-10.3687, -36.7052) -> (-4.5267, -36.7052)
  line L47 (-10.3687, -64.1372) -> (-10.3687, -36.7052)
  line L48 (-4.5267, -64.1372) -> (-10.3687, -64.1372)
  line L49 (-4.5267, -93.8552) -> (-4.5267, -64.1372)
  line L50 (-10.3687, -93.8552) -> (-4.5267, -93.8552)
  line L51 (-10.3687, -103.2462) -> (-10.3687, -93.8552)
  line L52 (87.4151, -108.2062) -> (-5.4087, -108.2062)
  circle C1 centre (11.2484, -100.5862) radius 3.175
  circle C2 centre (18.9474, -51.6912) radius 3.175
  circle C3 centre (26.6464, -47.2462) radius 3.175
  circle C4 centre (26.6464, -38.3562) radius 3.175
  circle C5 centre (34.3453, -33.9112) radius 3.175
  circle C6 centre (34.3453, -25.0212) radius 3.175
  circle C7 centre (42.0443, -20.5762) radius 3.175
  circle C8 centre (3.5495, -69.4712) radius 3.175
  circle C9 centre (3.5495, -60.5812) radius 3.175
  circle C10 centre (18.9474, -60.5812) radius 3.175
  circle C11 centre (11.2484, -65.0262) radius 3.175
  circle C12 centre (11.2484, -73.9162) radius 3.175
  circle C13 centre (3.5495, -78.3612) radius 3.175
  circle C14 centre (49.7433, -25.0212) radius 3.175
  circle C15 centre (42.0443, -29.4662) radius 3.175
  circle C16 centre (42.0443, -38.3562) radius 3.175
  circle C17 centre (34.3453, -42.8012) radius 3.175
  circle C18 centre (3.5495, -33.9112) radius 3.175
  circle C19 centre (18.9474, -25.0212) radius 3.175
  circle C20 centre (11.2484, -29.4662) radius 3.175
  circle C21 centre (11.2484, -38.3562) radius 3.175
  circle C22 centre (3.5495, -25.0212) radius 3.175
  circle C23 centre (11.2484, -20.5762) radius 3.175
  circle C24 centre (11.2484, -56.1362) radius 3.175
  circle C25 centre (11.2484, -47.2462) radius 3.175
  circle C26 centre (18.9474, -42.8012) radius 3.175
  circle C27 centre (18.9474, -33.9112) radius 3.175
  circle C28 centre (26.6464, -29.4662) radius 3.175
  circle C29 centre (26.6464, -20.5762) radius 3.175
  circle C30 centre (3.5495, -51.6912) radius 3.175
  circle C31 centre (3.5495, -42.8012) radius 3.175
  circle C32 centre (26.6464, -82.8062) radius 3.175
  circle C33 centre (18.9474, -87.2512) radius 3.175
  circle C34 centre (11.2484, -91.6962) radius 3.175
  circle C35 centre (3.5495, -96.1412) radius 3.175
  circle C36 centre (65.1412, -25.0212) radius 3.175
  circle C37 centre (65.1412, -33.9112) radius 3.175
  circle C38 centre (57.4422, -38.3562) radius 3.175
  circle C39 centre (57.4422, -47.2462) radius 3.175
  circle C40 centre (49.7433, -51.6912) radius 3.175
  circle C41 centre (49.7433, -60.5812) radius 3.175
  circle C42 centre (42.0443, -65.0262) radius 3.175
  circle C43 centre (42.0443, -73.9162) radius 3.175
  circle C44 centre (34.3453, -78.3612) radius 3.175
  circle C45 centre (34.3453, -87.2512) radius 3.175
  circle C46 centre (26.6464, -91.6962) radius 3.175
  circle C47 centre (18.9474, -96.1412) radius 3.175
  circle C48 centre (18.9474, -78.3612) radius 3.175
  circle C49 centre (11.2484, -82.8062) radius 3.175
  circle C50 centre (3.5495, -87.2512) radius 3.175
  circle C51 centre (57.4422, -20.5762) radius 3.175
  circle C52 centre (18.9474, -69.4712) radius 3.175
  circle C53 centre (26.6464, -65.0262) radius 3.175
  circle C54 centre (26.6464, -56.1362) radius 3.175
  circle C55 centre (34.3453, -51.6912) radius 3.175
  circle C56 centre (57.4422, -29.4662) radius 3.175
  circle C57 centre (49.7433, -33.9112) radius 3.175
  circle C58 centre (49.7433, -42.8012) radius 3.175
  circle C59 centre (42.0443, -47.2462) radius 3.175
  circle C60 centre (42.0443, -56.1362) radius 3.175
  circle C61 centre (34.3453, -60.5812) radius 3.175
  circle C62 centre (34.3453, -69.4712) radius 3.175
  circle C63 centre (26.6464, -73.9162) radius 3.175
  arc A1 centre (60.3808, 41.3579) radius 27.84 clockwise from (80.4032, 60.7014) to (80.4031, 22.0143)
  arc A2 centre (60.3809, 41.3578) radius 21.84 clockwise from (76.1597, 56.4579) to (76.1597, 26.2578)
  arc A3 centre (60.3808, 41.3579) radius 7.92 clockwise from (54.4515, 36.1073) to (54.4515, 46.6084)
  arc A4 centre (60.3809, 41.3579) radius 13.92 clockwise from (50.2044, 31.8602) to (50.2044, 50.8555)
  arc A5 centre (60.3809, 41.3578) radius 14.88 clockwise from (70.5577, 30.5022) to (50.204, 30.5022)
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extrude "Extrude6" cut sketch "Sketch128" profile of C2 C3 C4 C5 C6 C7 C14 C15 C16 C17 C19 C26 C27 C28 C29 C36 C37 C38 C39 C40 C41 C42 C43 C44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 distance 10
combine "Combine1"
offset_faces "OffsetFaces2" distance 146
delete_face "DeleteFace16"
fillet "Fillet1" radius 7.5
move "Move7"
copy_paste_bodies "CopyPasteBodies1"
move "Move8"
copy_paste_bodies "CopyPasteBodies2"
move "Move9"
copy_paste_bodies "CopyPasteBodies3"
move "Move10"
sketch "Sketch129" plane through (0, 124.2387, 0) normal (0, -1, 0) x axis (1, 0, 0)
  circle C1 centre (26.5037, -100.5859) radius 3.175
extrude "Extrude27" cut sketch "Sketch129" against normal blind 10
sketch "Sketch130" plane through (0, 124.2387, 0) normal (0, -1, 0) x axis (1, 0, 0)
  circle C1 centre (26.6058, -91.6959) radius 3.175
extrude "Extrude28" cut sketch "Sketch130" against normal blind 10
sketch "Sketch131" plane through (0, 124.2387, 0) normal (0, -1, 0) x axis (1, 0, 0)
  circle C1 centre (18.9068, -87.2509) radius 3.175
extrude "Extrude29" cut sketch "Sketch131" against normal blind 10
sketch "Sketch132" plane through (0, 124.2387, 0) normal (0, -1, 0) x axis (1, 0, 0)
  circle C1 centre (26.6058, -82.8059) radius 3.175
extrude "Extrude30" cut sketch "Sketch132" against normal blind 10
sketch "Sketch133" plane through (0, 124.2387, 0) normal (0, -1, 0) x axis (1, 0, 0)
  circle C1 centre (34.3047, -78.3609) radius 3.175
extrude "Extrude31" cut sketch "Sketch133" against normal blind 10
sketch "Sketch134" plane through (0, 124.2387, 0) normal (0, -1, 0) x axis (1, 0, 0)
  circle C1 centre (34.3089, -60.5809) radius 3.175
extrude "Extrude32" cut sketch "Sketch134" against normal blind 10
sketch "Sketch135" plane through (0, 124.2387, 0) normal (0, -1, 0) x axis (1, 0, 0)
  circle C1 centre (34.3089, -51.6909) radius 3.175
extrude "Extrude33" cut sketch "Sketch135" against normal blind 10
sketch "Sketch136" plane through (0, 124.2387, 0) normal (0, -1, 0) x axis (1, 0, 0)
  circle C1 centre (42.0078, -47.2459) radius 3.175
extrude "Extrude34" cut sketch "Sketch136" against normal blind 10
sketch "Sketch137" plane through (0, 124.2387, 0) normal (0, -1, 0) x axis (1, 0, 0)
  circle C1 centre (42.0078, -38.3559) radius 3.175
extrude "Extrude35" cut sketch "Sketch137" against normal blind 10
sketch "Sketch138" plane through (0, 124.2387, 0) normal (0, -1, 0) x axis (1, 0, 0)
  circle C1 centre (49.7068, -25.0209) radius 3.175
extrude "Extrude36" cut sketch "Sketch138" against normal blind 10
sketch "Sketch139" plane through (0, 124.2387, 0) normal (0, -1, 0) x axis (1, 0, 0)
  circle C1 centre (57.4058, -20.5759) radius 3.175
extrude "Extrude37" cut sketch "Sketch139" against normal blind 10
sketch "Sketch140" plane through (0, 124.2387, 0) normal (0, -1, 0) x axis (1, 0, 0)
  circle C1 centre (57.4058, -29.4659) radius 3.175
extrude "Extrude38" cut sketch "Sketch140" against normal blind 10
sketch "Sketch141" plane through (0, 124.2387, 0) normal (0, -1, 0) x axis (1, 0, 0)
  circle C1 centre (49.7068, -33.9109) radius 3.175
extrude "Extrude39" cut sketch "Sketch141" against normal blind 10
sketch "Sketch142" plane through (0, 124.2387, 0) normal (0, -1, 0) x axis (1, 0, 0)
  circle C1 centre (88.2342, -100.5862) radius 3.175
extrude "Extrude40" cut sketch "Sketch142" against normal blind 10
sketch "Sketch143" plane through (0, 124.2387, 0) normal (0, -1, 0) x axis (1, 0, 0)
  circle C1 centre (95.9332, -96.1412) radius 3.175
extrude "Extrude41" cut sketch "Sketch143" against normal blind 10
sketch "Sketch144" plane through (0, 124.2387, 0) normal (0, -1, 0) x axis (1, 0, 0)
  circle C1 centre (95.9332, -87.2512) radius 3.175
extrude "Extrude42" cut sketch "Sketch144" against normal blind 10
sketch "Sketch145" plane through (0, 124.2387, 0) normal (0, -1, 0) x axis (1, 0, 0)
  circle C1 centre (88.2342, -91.6962) radius 3.175
extrude "Extrude43" cut sketch "Sketch145" against normal blind 10
sketch "Sketch146" plane through (0, 124.2387, 0) normal (0, -1, 0) x axis (1, 0, 0)
  circle C1 centre (80.5027, -96.1409) radius 3.175
extrude "Extrude44" cut sketch "Sketch146" against normal blind 10
sketch "Sketch147" plane through (0, 124.2387, 0) normal (0, -1, 0) x axis (1, 0, 0)
  circle C1 centre (72.8037, -100.5859) radius 3.175
extrude "Extrude45" cut sketch "Sketch147" against normal blind 10
sketch "Sketch148" plane through (0, 124.2387, 0) normal (0, -1, 0) x axis (1, 0, 0)
  circle C1 centre (95.9332, -78.3612) radius 3.175
extrude "Extrude46" cut sketch "Sketch148" against normal blind 10
sketch "Sketch149" plane through (0, 124.2387, 0) normal (0, -1, 0) x axis (1, 0, 0)
  circle C1 centre (88.2342, -82.8062) radius 3.175
extrude "Extrude47" cut sketch "Sketch149" against normal blind 10
delete_face "DeleteFace1"
sketch "Sketch150" plane through (0, 124.2387, 0) normal (0, -1, 0) x axis (1, 0, 0)
  circle C1 centre (72.8037, -20.5759) radius 3.175
extrude "Extrude48" cut sketch "Sketch150" against normal blind 30
sketch "Sketch151" plane through (0, 124.2387, 0) normal (0, -1, 0) x axis (1, 0, 0)
  circle C1 centre (57.4342, -100.5862) radius 3.175
extrude "Extrude49" cut sketch "Sketch151" against normal blind 14
remove_body "RemoveBody29"
remove_body "RemoveBody30"
remove_body "RemoveBody31"
remove_body "RemoveBody32"
remove_body "RemoveBody33"
remove_body "RemoveBody34"
remove_body "RemoveBody35"
remove_body "RemoveBody36"
remove_body "RemoveBody37"
remove_body "RemoveBody38"
remove_body "RemoveBody39"
remove_body "RemoveBody40"
remove_body "RemoveBody41"
remove_body "RemoveBody42"
remove_body "RemoveBody43"
remove_body "RemoveBody44"
remove_body "RemoveBody45"
remove_body "RemoveBody46"
remove_body "RemoveBody47"
remove_body "RemoveBody48"
remove_body "RemoveBody49"
remove_body "RemoveBody50"
remove_body "RemoveBody51"
remove_body "RemoveBody52"
remove_body "RemoveBody53"
remove_body "RemoveBody54"
remove_body "RemoveBody55"
remove_body "RemoveBody56"
remove_body "RemoveBody57"
remove_body "RemoveBody58"
remove_body "RemoveBody59"
remove_body "RemoveBody60"
remove_body "RemoveBody61"
remove_body "RemoveBody62"
remove_body "RemoveBody63"
remove_body "RemoveBody64"
remove_body "RemoveBody65"
remove_body "RemoveBody66"
remove_body "RemoveBody67"
remove_body "RemoveBody68"
remove_body "RemoveBody69"
remove_body "RemoveBody70"
remove_body "RemoveBody71"
remove_body "RemoveBody72"
remove_body "RemoveBody73"
remove_body "RemoveBody74"
remove_body "RemoveBody75"
remove_body "RemoveBody76"
remove_body "RemoveBody77"
remove_body "RemoveBody78"
remove_body "RemoveBody79"
remove_body "RemoveBody80"
remove_body "RemoveBody81"
remove_body "RemoveBody82"
remove_body "RemoveBody83"
remove_body "RemoveBody84"
remove_body "RemoveBody85"
remove_body "RemoveBody86"
remove_body "RemoveBody87"
remove_body "RemoveBody88"
remove_body "RemoveBody89"
remove_body "RemoveBody90"
remove_body "RemoveBody91"
remove_body "RemoveBody92"
remove_body "RemoveBody93"
remove_body "RemoveBody94"
remove_body "RemoveBody95"
remove_body "RemoveBody96"
remove_body "RemoveBody97"
remove_body "RemoveBody98"
remove_body "RemoveBody99"
remove_body "RemoveBody100"
remove_body "RemoveBody101"
remove_body "RemoveBody102"
remove_body "RemoveBody103"
remove_body "RemoveBody104"
remove_body "RemoveBody105"
remove_body "RemoveBody106"
remove_body "RemoveBody107"
remove_body "RemoveBody108"
remove_body "RemoveBody109"
remove_body "RemoveBody110"
remove_body "RemoveBody111"
remove_body "RemoveBody112"
remove_body "RemoveBody113"
remove_body "RemoveBody114"
remove_body "RemoveBody115"
remove_body "RemoveBody116"
remove_body "RemoveBody117"
remove_body "RemoveBody118"
remove_body "RemoveBody119"
remove_body "RemoveBody120"
remove_body "RemoveBody121"
remove_body "RemoveBody122"
remove_body "RemoveBody123"
remove_body "RemoveBody124"
remove_body "RemoveBody125"
remove_body "RemoveBody126"
remove_body "RemoveBody127"
remove_body "RemoveBody128"
remove_body "RemoveBody129"
remove_body "RemoveBody130"
remove_body "RemoveBody131"
remove_body "RemoveBody132"
remove_body "RemoveBody133"
remove_body "RemoveBody134"
remove_body "RemoveBody135"
remove_body "RemoveBody136"
remove_body "RemoveBody137"
remove_body "RemoveBody138"
remove_body "RemoveBody139"
remove_body "RemoveBody140"
remove_body "RemoveBody141"
remove_body "RemoveBody142"
remove_body "RemoveBody143"
remove_body "RemoveBody144"
remove_body "RemoveBody145"
remove_body "RemoveBody146"
remove_body "RemoveBody147"
remove_body "RemoveBody148"
remove_body "RemoveBody149"
remove_body "RemoveBody150"
remove_body "RemoveBody151"
remove_body "RemoveBody152"
remove_body "RemoveBody153"
remove_body "RemoveBody154"
remove_body "RemoveBody155"
remove_body "RemoveBody156"
remove_body "RemoveBody157"
remove_body "RemoveBody158"
remove_body "RemoveBody159"
remove_body "RemoveBody160"
remove_body "RemoveBody161"
remove_body "RemoveBody162"
remove_body "RemoveBody163"
remove_body "RemoveBody164"
remove_body "RemoveBody165"
remove_body "RemoveBody166"
remove_body "RemoveBody167"
remove_body "RemoveBody168"
remove_body "RemoveBody169"
remove_body "RemoveBody170"
remove_body "RemoveBody171"
base_feature "Base Feature1"
component_insert "Component Insert15"
remove_instance "RemoveInstance6"
position "Position6"
mirror "Mirror1" mirrorStitchTolerance 0.1
move "Move1"
copy_paste_bodies "CopyPasteBodies4"
move "Move11"
move "Move12"
combine "Combine1"
position "Position7"
sketch "Sketch152" plane through (0, 127.2387, 0) normal (0, -1, 0) x axis (1, 0, 0)
  line L1 (-5.4087, -110.7462) -> (106.3913, -110.7462)
  line L2 (-12.9087, 73.7538) -> (-12.9087, -103.2462)
  line L3 (106.3913, 81.2538) -> (-5.4087, 81.2538)
  line L4 (113.8913, -103.2462) -> (113.8913, 73.7538)
  line L5 (126.1913, 41.3578) -> (126.1913, -103.2462)
  line L6 (126.3913, 41.3578) -> (126.1913, 41.3578)
  line L7 (126.3913, 82.7538) -> (126.3913, 41.3578)
  line L8 (-5.4087, 102.7538) -> (106.3913, 102.7538)
  line L9 (-25.4087, -103.2462) -> (-25.4087, 82.7538)
  line L10 (106.1913, -123.2462) -> (-5.4087, -123.2462)
  arc A1 centre (-5.4087, -103.2462) radius 7.5 clockwise from (-5.4087, -110.7462) to (-12.9087, -103.2462)
  arc A2 centre (-5.4087, 73.7538) radius 7.5 clockwise from (-12.9087, 73.7538) to (-5.4087, 81.2538)
  arc A3 centre (106.3913, 73.7538) radius 7.5 clockwise from (106.3913, 81.2538) to (113.8913, 73.7538)
  arc A4 centre (106.3913, -103.2462) radius 7.5 clockwise from (113.8913, -103.2462) to (106.3913, -110.7462)
  arc A5 centre (105.5913, 88.3538) radius 2.6 clockwise from (105.4913, 85.7557) to (105.4913, 90.9519)
  arc A6 centre (105.3913, 88.3538) radius 2.6 clockwise from (105.4913, 90.9519) to (105.4913, 85.7557)
  circle C1 centre (-4.6087, 88.3538) radius 2.6
  circle C2 centre (3.3413, -118.1462) radius 2.6
  circle C3 centre (-20.4087, -77.2462) radius 2.6
  circle C4 centre (-20.4087, 2.7088) radius 2.6
  arc A7 centre (106.1913, -103.2462) radius 20 clockwise from (126.1913, -103.2462) to (106.1913, -123.2462)
  arc A8 centre (106.3913, 73.7538) radius 21.9317 clockwise from (106.3913, 102.7538) to (126.3913, 82.7538)
  arc A9 centre (-5.4087, 73.7538) radius 29 clockwise from (-25.4087, 82.7538) to (-5.4087, 102.7538)
  arc A10 centre (-5.4087, -103.2462) radius 20 clockwise from (-5.4087, -123.2462) to (-25.4087, -103.2462)
  circle C5 centre (121.1913, 2.7088) radius 2.6
  circle C6 centre (121.1913, -77.2462) radius 2.6
  circle C7 centre (97.4413, -118.1462) radius 2.6
extrude "Extrude30" add sketch "Sketch152" against normal blind 2.54
move "Move2"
